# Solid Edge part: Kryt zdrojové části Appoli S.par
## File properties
Username: petr.kostka
Typ obsahu dokumentu: 0
Title: Kryt zdrojové části Appoli S
Author: petr.kostka
Keywords: ---
Template: Part Robe 03_24.par
Last saved by: petr.kostka
Revision: 43
Application: Solid Edge
Company: 19030930-01M
Hustota: 2680,000 kg/m^3
Přesnost: 0,990
Material: LM6 - slitina hliníku
Face Style: Model Default
Fill Style: Normal
Virtual Style: Normal
Skupiny: Slitiny hliníku
LibraryName: Robe knihovna - Konstrukce
Coef. of Thermal Exp: 0.0
Thermal Conductivity: 0.0
Specific Heat: 0.0
Modulus of Elasticity: 0.0
Poisson's Ratio: 0.0
Yield Stress: 0.0
Ultimate Stress: 0.0
Elongation: 0.0
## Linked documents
sti Appoli S.par
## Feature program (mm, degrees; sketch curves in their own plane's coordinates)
part copy "KopírovanáSoučást_2"
sketch for "Vyříznutí_1" plane through (0, -0.5, 0) normal (0, -1, 0) x-axis (-1, 0, 0)
  line (-75.247, -73.3865) -> (-75.247, 73.3865)
  line (-75.247, 73.3865) -> (75.247, 73.3865)
  line (75.247, 73.3865) -> (75.247, -73.3865)
  line (75.247, -73.3865) -> (-75.247, -73.3865)
extrude "Vyříznutí_1" cut finite 10 along +normal
delete faces "unnamed DeleteFaces 1"
sketch for "Vysunutí_2" plane through (0, -0.5, 0) normal (0, -1, 0) x-axis (-1, 0, 0)
  line (-51.8429, -36.8441) -> (-51.8429, 36.8441)
  line (-49.8441, 38.8429) -> (-47.8374, 38.8429)
  line (-38.8429, 47.8374) -> (-38.8429, 49.8441)
  line (-36.8441, 51.8429) -> (36.8441, 51.8429)
  line (38.8429, 47.8374) -> (38.8429, 49.8441)
  line (49.8441, 38.8429) -> (47.8374, 38.8429)
  line (51.8429, 36.8441) -> (51.8429, -36.8441)
  line (47.8374, -38.8429) -> (49.8441, -38.8429)
  line (38.8429, -49.8441) -> (38.8429, -47.8374)
  line (36.8441, -51.8429) -> (-36.8441, -51.8429)
  line (-38.8429, -47.8374) -> (-38.8429, -49.8441)
  line (-49.8441, -38.8429) -> (-47.8374, -38.8429)
extrude "Vysunutí_2" add finite 10.5 along -normal
delete faces "unnamed DeleteFaces 2"
delete faces "unnamed DeleteFaces 3"
delete faces "unnamed DeleteFaces 4"
delete faces "unnamed DeleteFaces 5"
delete faces "unnamed DeleteFaces 6"
sketch for "Vysunutí_3" plane through (-0.0001, 0, 0.0002) normal (0, -1, 0) x-axis (1, 0, 0)
  arc centre (-41.4999, 41.4998) radius 17 from (-41.4999, 58.4998) to (-58.4999, 41.4998) ccw
  line (-58.4999, 41.4998) -> (-58.4999, -41.5002)
  arc centre (-41.4999, -41.5002) radius 17 from (-41.4999, -58.5002) to (-58.4999, -41.5002) cw
  line (-41.4999, -58.5002) -> (41.5001, -58.5002)
  arc centre (41.5001, -41.5002) radius 17 from (58.5001, -41.5002) to (41.5001, -58.5002) cw
  line (58.5001, -41.5002) -> (58.5001, 41.4998)
  arc centre (41.5001, 41.4998) radius 17 from (41.5001, 58.4998) to (58.5001, 41.4998) cw
  line (41.5001, 58.4998) -> (-41.4999, 58.4998)
extrude "Vysunutí_3" add finite 2 along -normal
sketch for "Vysunutí_4" plane through (0.065, 13, -29.5) normal (0, 1, 0) x-axis (-1, 0, 0)
  line (-43.285, 14) -> (-43.285, -14)
  arc centre (-39.785, -14) radius 3.5 from (-43.285, -14) to (-39.785, -17.5) ccw
  line (-39.785, -17.5) -> (39.885, -17.5)
  arc centre (39.885, -14.1) radius 3.4 from (39.885, -17.5) to (43.285, -14.1) ccw
  line (43.285, 12.1) -> (43.285, -14.1)
  arc centre (39.885, 12.1) radius 3.4 from (43.285, 12.1) to (39.885, 15.5) ccw
  line (13.065, 15.5) -> (39.885, 15.5)
  arc centre (13.065, 17) radius 1.5 from (13.065, 15.5) to (11.6508, 16.5) cw
  arc centre (10.2366, 16) radius 1.5 from (11.6508, 16.5) to (10.2366, 17.5) ccw
  line (10.2366, 17.5) -> (-39.785, 17.5)
  arc centre (-39.785, 14) radius 3.5 from (-39.785, 17.5) to (-43.285, 14) ccw
extrude "Vysunutí_4" add finite 5 along -normal
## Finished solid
Body 1: solid body, 420 faces, 991 edges, 578 vertices.
  Faces by surface: blend 181, cylinder 70, swept 51, plane 48, spline 36, cone 14, torus 12, spun 8
  Edges by curve: intersection 403, line 186, circle 183, curve on surface 92, ellipse 80, spline 47
Bounding box of the edges (mm; curved faces can reach further): 119.088 x 13.500 x 119.556, from (-59.5438, -0.5, -59.778) to (59.5444, 13, 59.7783).
Cylindrical faces by radius (mm): R0.5 x70
Conical faces (half-angle, radius in mm at the cone's reference point): 1.5 deg R1.5 x2, 1.5 deg R3.4 x2, 1.5 deg R3.5 x2, 3 deg R5 x4, 8 deg R11.5 x4
Toroidal faces (ring radius, tube radius in mm): R3.9133 r0.5 x2, R4.0133 r0.5 x2, R4.7628 r0.25 x4, R5.6303 r0.25 x4
Planar faces by outward normal: +y 29, -y 6, oblique 13
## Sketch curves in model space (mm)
arc centre (39.85, 13, -43.5) radius 3.5 from (43.35, 13, -43.5) through (42.2518, 13, -46.0458) to (39.85, 13, -47)
line (39.85, 13, -47) -> (-39.82, 13, -47)
arc centre (-39.82, 13, -43.6) radius 3.4 from (-39.82, 13, -47) through (-42.2931, 13, -45.9332) to (-43.22, 13, -43.6)
line (-43.22, 13, -17.4) -> (-43.22, 13, -43.6)
arc centre (-39.82, 13, -17.4) radius 3.4 from (-43.22, 13, -17.4) through (-42.1532, 13, -14.9269) to (-39.82, 13, -14)
line (-13, 13, -14) -> (-39.82, 13, -14)
arc centre (-13, 13, -12.5) radius 1.5 from (-13, 13, -14) through (-12.0985, 13, -13.6988) to (-11.5858, 13, -13)
arc centre (-10.1716, 13, -13.5) radius 1.5 from (-11.5858, 13, -13) through (-11.0013, 13, -12.2504) to (-10.1716, 13, -12)
line (-10.1716, 13, -12) -> (39.85, 13, -12)
arc centre (39.85, 13, -15.5) radius 3.5 from (39.85, 13, -12) through (42.3958, 13, -13.0982) to (43.35, 13, -15.5)
line (43.35, 13, -15.5) -> (43.35, 13, -43.5)
arc centre (41.5, 0, -41.5) radius 17 from (58.5, 0, -41.5) through (53.1661, 0, -53.8654) to (41.5, 0, -58.5)
line (58.5, 0, -41.5) -> (58.5, 0, 41.5)
arc centre (41.5, 0, 41.5) radius 17 from (41.5, 0, 58.5) through (53.8654, 0, 53.1661) to (58.5, 0, 41.5)
line (41.5, 0, 58.5) -> (-41.5, 0, 58.5)
arc centre (-41.5, 0, 41.5) radius 17 from (-41.5, 0, 58.5) through (-53.8654, 0, 53.1661) to (-58.5, 0, 41.5)
line (-58.5, 0, 41.5) -> (-58.5, 0, -41.5)
arc centre (-41.5, 0, -41.5) radius 17 from (-41.5, 0, -58.5) through (-53.8654, 0, -53.1661) to (-58.5, 0, -41.5)
line (-41.5, 0, -58.5) -> (41.5, 0, -58.5)
ellipse centre (49.8416, -0.5, -36.8416) radii 2.0024, 2 from (51.8429, -0.5, -36.8441) through (51.2159, -0.5, -38.2981) to (49.8441, -0.5, -38.8429)
line (49.8441, -0.5, -38.8429) -> (47.8374, -0.5, -38.8429)
ellipse centre (47.8483, -0.5, -47.8483) radii 9.011, 9 from (47.8374, -0.5, -38.8429) through (41.2944, -0.5, -41.6643) to (38.8429, -0.5, -47.8374)
line (38.8429, -0.5, -47.8374) -> (38.8429, -0.5, -49.8441)
ellipse centre (36.8416, -0.5, -49.8416) radii 2.0024, 2 from (36.8441, -0.5, -51.8429) through (38.2981, -0.5, -51.2159) to (38.8429, -0.5, -49.8441)
line (36.8441, -0.5, -51.8429) -> (-36.8441, -0.5, -51.8429)
ellipse centre (-36.8416, -0.5, -49.8416) radii 2.0024, 2 from (-36.8441, -0.5, -51.8429) through (-38.2981, -0.5, -51.2159) to (-38.8429, -0.5, -49.8441)
line (-38.8429, -0.5, -47.8374) -> (-38.8429, -0.5, -49.8441)
ellipse centre (-47.8483, -0.5, -47.8483) radii 9.011, 9 from (-47.8374, -0.5, -38.8429) through (-41.2944, -0.5, -41.6643) to (-38.8429, -0.5, -47.8374)
line (-49.8441, -0.5, -38.8429) -> (-47.8374, -0.5, -38.8429)
ellipse centre (-49.8416, -0.5, -36.8416) radii 2.0024, 2 from (-51.8429, -0.5, -36.8441) through (-51.2159, -0.5, -38.2981) to (-49.8441, -0.5, -38.8429)
line (-51.8429, -0.5, -36.8441) -> (-51.8429, -0.5, 36.8441)
ellipse centre (-49.8416, -0.5, 36.8416) radii 2.0024, 2 from (-51.8429, -0.5, 36.8441) through (-51.2159, -0.5, 38.2981) to (-49.8441, -0.5, 38.8429)
line (-47.8374, -0.5, 38.8429) -> (-49.8441, -0.5, 38.8429)
ellipse centre (-47.8483, -0.5, 47.8483) radii 9.011, 9 from (-38.8429, -0.5, 47.8374) through (-41.6643, -0.5, 41.2944) to (-47.8374, -0.5, 38.8429)
line (-38.8429, -0.5, 49.8441) -> (-38.8429, -0.5, 47.8374)
ellipse centre (-36.8416, -0.5, 49.8416) radii 2.0024, 2 from (-36.8441, -0.5, 51.8429) through (-38.2981, -0.5, 51.2159) to (-38.8429, -0.5, 49.8441)
line (-36.8441, -0.5, 51.8429) -> (36.8441, -0.5, 51.8429)
ellipse centre (36.8416, -0.5, 49.8416) radii 2.0024, 2 from (36.8441, -0.5, 51.8429) through (38.2981, -0.5, 51.2159) to (38.8429, -0.5, 49.8441)
line (38.8429, -0.5, 47.8374) -> (38.8429, -0.5, 49.8441)
ellipse centre (47.8483, -0.5, 47.8483) radii 9.011, 9 from (47.8374, -0.5, 38.8429) through (41.2944, -0.5, 41.6643) to (38.8429, -0.5, 47.8374)
line (49.8441, -0.5, 38.8429) -> (47.8374, -0.5, 38.8429)
ellipse centre (49.8416, -0.5, 36.8416) radii 2.0024, 2 from (51.8429, -0.5, 36.8441) through (51.2159, -0.5, 38.2981) to (49.8441, -0.5, 38.8429)
line (51.8429, -0.5, 36.8441) -> (51.8429, -0.5, -36.8441)
line (-75.247, -0.5, -73.3865) -> (-75.247, -0.5, 73.3865)
line (-75.247, -0.5, 73.3865) -> (75.247, -0.5, 73.3865)
line (75.247, -0.5, 73.3865) -> (75.247, -0.5, -73.3865)
line (75.247, -0.5, -73.3865) -> (-75.247, -0.5, -73.3865)
arc centre (41, 0, -41) radius 15 from (56, 0, -41) through (51.2936, 0, -51.9106) to (41, 0, -56)
line (56, 0, -41) -> (56, 0, 41)
arc centre (41, 0, 41) radius 15 from (41, 0, 56) through (51.9106, 0, 51.2936) to (56, 0, 41)
line (41, 0, 56) -> (-41, 0, 56)
arc centre (-41, 0, 41) radius 15 from (-56, 0, 41) through (-51.2936, 0, 51.9106) to (-41, 0, 56)
line (-56, 0, 41) -> (-56, 0, -41)
arc centre (-41, 0, -41) radius 15 from (-41, 0, -56) through (-51.9106, 0, -51.2936) to (-56, 0, -41)
line (-41, 0, -56) -> (41, 0, -56)
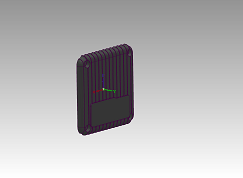
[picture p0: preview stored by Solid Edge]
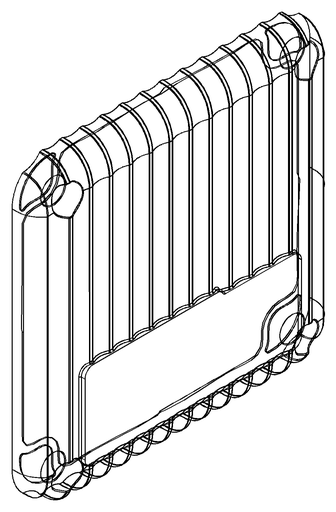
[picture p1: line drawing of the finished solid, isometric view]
